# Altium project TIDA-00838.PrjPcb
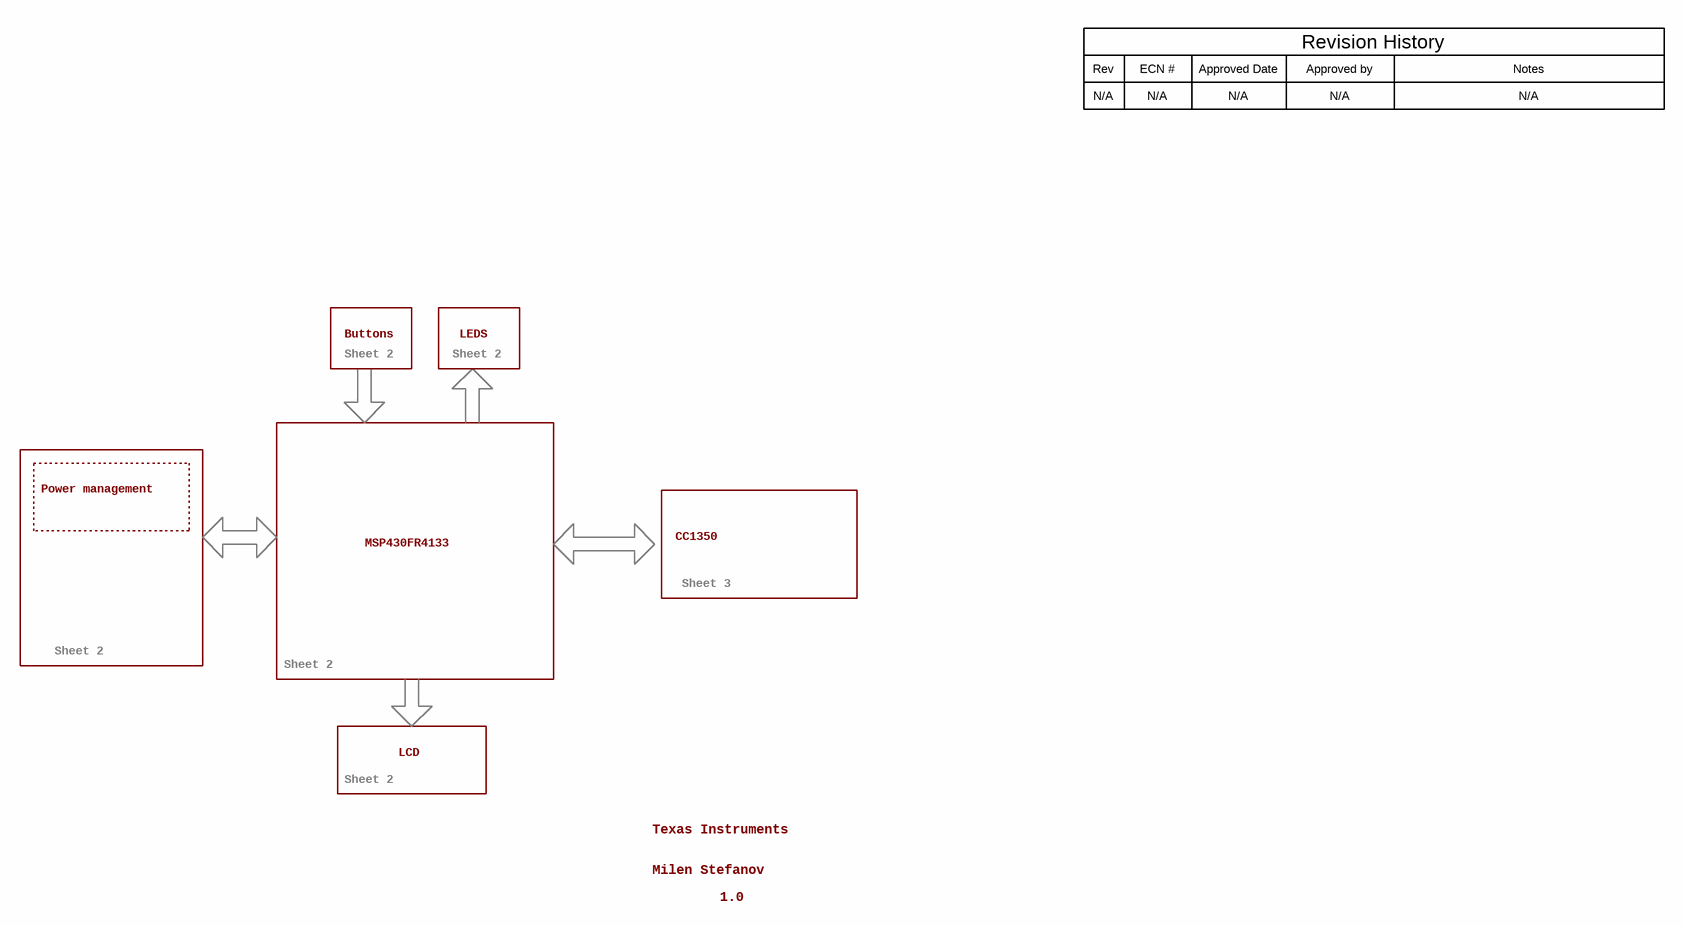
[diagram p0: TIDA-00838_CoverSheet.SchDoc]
TID: TIDA-00838; TechSupport: http://www.ti.com/support; SCH_Rev: E1; PRJ_Title: Heat Cost Allocator with wM-Bus @ 868MHz; PRJ_Number: TIDA-00838; PRJ_Engineer: Milen Stefanov; PRJ_Customer: Public Release; PCB_Rev: E1; PCB_Layout: a0797195; EVM_Orderable: N/A; CopyrightYear: 2015
4 sheets, 91 parts. Net scope: global (net labels, ports and power ports of the same name join across sheets).
Board file: TIDA-00838.PcbDoc
Sheets:
  TIDA-00838_CoverSheet.SchDoc
  TIDA-00838_TID_Hardware.SchDoc
  TIDA-00838_MCU.SchDoc
  TIDA-00838_RF.SchDoc

## Sheet TIDA-00838_CoverSheet.SchDoc
size 431 x 279 mm; Date: Not shown in title block; ApprovedBy: Not shown in title block; CheckedBy: Not shown in title block; Author: Not shown in title block; CompanyName: Not shown in title block; Engineer: Not shown in title block; Organization: Not shown in title block; Address1: Not shown in title block; Address2: Not shown in title block; Address3: Not shown in title block; Address4: Not shown in title block; DocumentNumber: 1; Revision: Use project parameter SCH_Rev; SheetNumber: 1; SheetTotal: 3; PageSetup: Record=PageOptions¦CenterHorizontal=True¦CenterVertical=True¦PrintScale=1.00¦XCorrection=1.00¦YCorrection=1.00¦PrintKind=0¦BorderSize=5000000¦LeftOffset=0¦BottomOffset=0¦Orientation=2¦PaperLength=1000¦PaperWidth=1000¦Scale=100¦PaperSource=15¦PrintQuality=600¦MediaType=1¦DitherType=10¦PaperKind=Letter¦PrintScaleMode=1

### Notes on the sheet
- Rev
- N/A
- ECN #
- Approved Date
- Approved by
- Revision History
- Notes
- Buttons
- Sheet 2
- LEDS
- Power management
- MSP430FR4133
- CC1350
- Sheet 3
- LCD
- Texas Instruments
- Milen Stefanov
- 1.0

## Sheet TIDA-00838_TID_Hardware.SchDoc
size 431 x 279 mm; Date: Not shown in title block; ApprovedBy: Not shown in title block; CheckedBy: Not shown in title block; Author: Not shown in title block; CompanyName: Not shown in title block; Engineer: Not shown in title block; Organization: Not shown in title block; Address1: Not shown in title block; Address2: Not shown in title block; Address3: Not shown in title block; Address4: Not shown in title block; DocumentNumber: 1; Revision: Use project parameter SCH_Rev; SheetNumber: 3; SheetTotal: 3; PageSetup: Record=PageOptions¦CenterHorizontal=True¦CenterVertical=True¦PrintScale=1.00¦XCorrection=1.00¦YCorrection=1.00¦PrintKind=0¦BorderSize=5000000¦LeftOffset=0¦BottomOffset=0¦Orientation=2¦PaperLength=1000¦PaperWidth=1000¦Scale=100¦PaperSource=15¦PrintQuality=600¦MediaType=1¦DitherType=10¦PaperKind=Letter¦PrintScaleMode=1
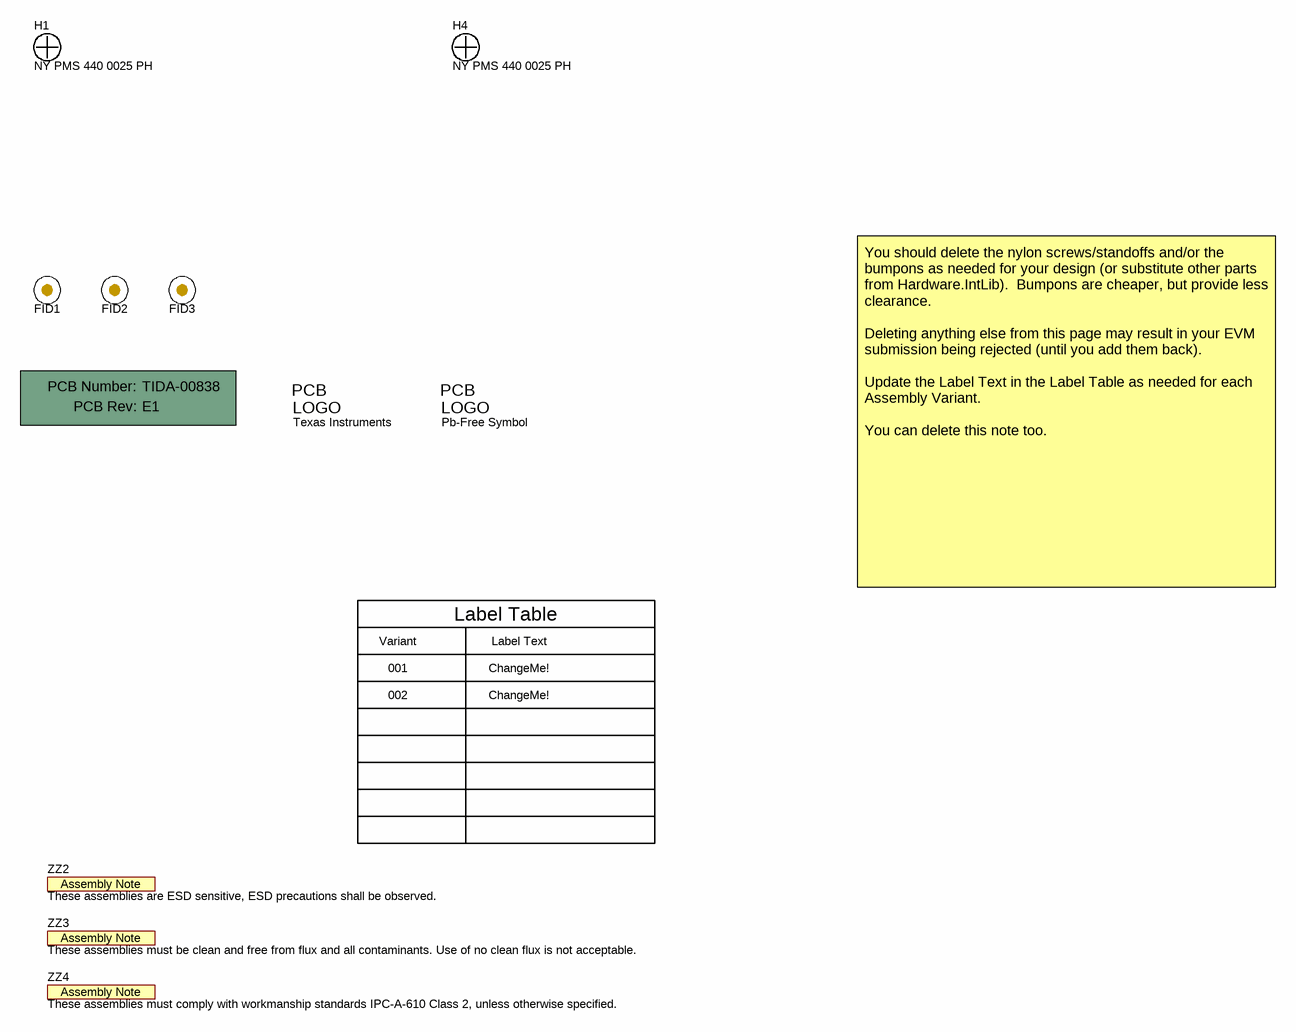
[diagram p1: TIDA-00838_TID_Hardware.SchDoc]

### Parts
!PCB  Printed Circuit Board  (value not drawn)  (mechanical)
FID1  Fiducial  [Fiducial10-20]  (value not drawn)
FID2  Fiducial  [Fiducial10-20]  (value not drawn)
FID3  Fiducial  [Fiducial10-20]  (value not drawn)
H1  NY PMS 440 0025 PH  [NY PMS 440 0025 PH]
H4  NY PMS 440 0025 PH  [NY PMS 440 0025 PH]
Logo1  Texas Instruments  [TI_Symbol_Overlay_Small]  (no BOM)
Logo2  Pb-Free Symbol  [Pb-Free_Overlay_Small]  (no BOM)
ZZ2  These assemblies are ESD sensitive, ESD precautions shall be observed.  [AssemblyNote]  (no BOM)
ZZ3  These assemblies must be clean and free from flux and all contaminants. Use of no clean flux is not acceptable.  [AssemblyNote]  (no BOM)
ZZ4  These assemblies must comply with workmanship standards IPC-A-610 Class 2, unless otherwise specified.  [AssemblyNote]  (no BOM)

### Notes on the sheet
- Variant
- Label Table
- Label Text
- You should delete the nylon screws/standoffs and/or the bumpons as needed for your design (or substitute other parts from Hardware.IntLib).  Bumpons are cheaper, but provide less clearance.
  Deleting anything else from this page may result in your EVM submission being rejected (until you add them back).
  Update the Label Text in the Label Table as needed for each Assembly Variant.
  You can delete this note too.
- 001
- 002
- ChangeMe!

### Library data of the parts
!PCB = PCB: Manufacturer: Any; PartNumber: TIDA-00838; SymbolCreator: a0412235
FID1-FID3 = Fiducial: Fiducial mark.  There is nothing to buy or mount.; SymbolCreator: codlsc
H1 H4 = NY PMS 440 0025 PH: Machine Screw, Round, #4-40 x 1/4, Nylon, Philips panhead; Manufacturer: B&F Fastener Supply; CompType: Hardware; SymbolCreator: codlsc; U/M: EA
Logo1 = TI_Logo: Texas Instrument Corporate Signature; SymbolCreator: codlsc
Logo2 = Pb-Free: SymbolCreator: a0412235
ZZ2-ZZ4 = AssemblyNote: SymbolCreator: codlsc

## Sheet TIDA-00838_MCU.SchDoc
size 431 x 279 mm; Date: Not shown in title block; ApprovedBy: Not shown in title block; CheckedBy: Not shown in title block; Author: Not shown in title block; CompanyName: Not shown in title block; Engineer: Not shown in title block; Organization: Not shown in title block; Address1: Not shown in title block; Address2: Not shown in title block; Address3: Not shown in title block; Address4: Not shown in title block; DocumentNumber: 1; Revision: Use project parameter SCH_Rev; SheetNumber: 2; SheetTotal: 3; PageSetup: Record=PageOptions¦CenterHorizontal=True¦CenterVertical=True¦PrintScale=0.62¦XCorrection=1.00¦YCorrection=1.00¦PrintKind=0¦BorderSize=5000000¦LeftOffset=0¦BottomOffset=0¦Orientation=2¦PaperLength=2794¦PaperWidth=2159¦Scale=100¦PaperSource=7¦PrintQuality=600¦MediaType=1¦DitherType=10¦PrintScaleMode=1¦PaperKind=8 1/2x11¦PaperIndex=1
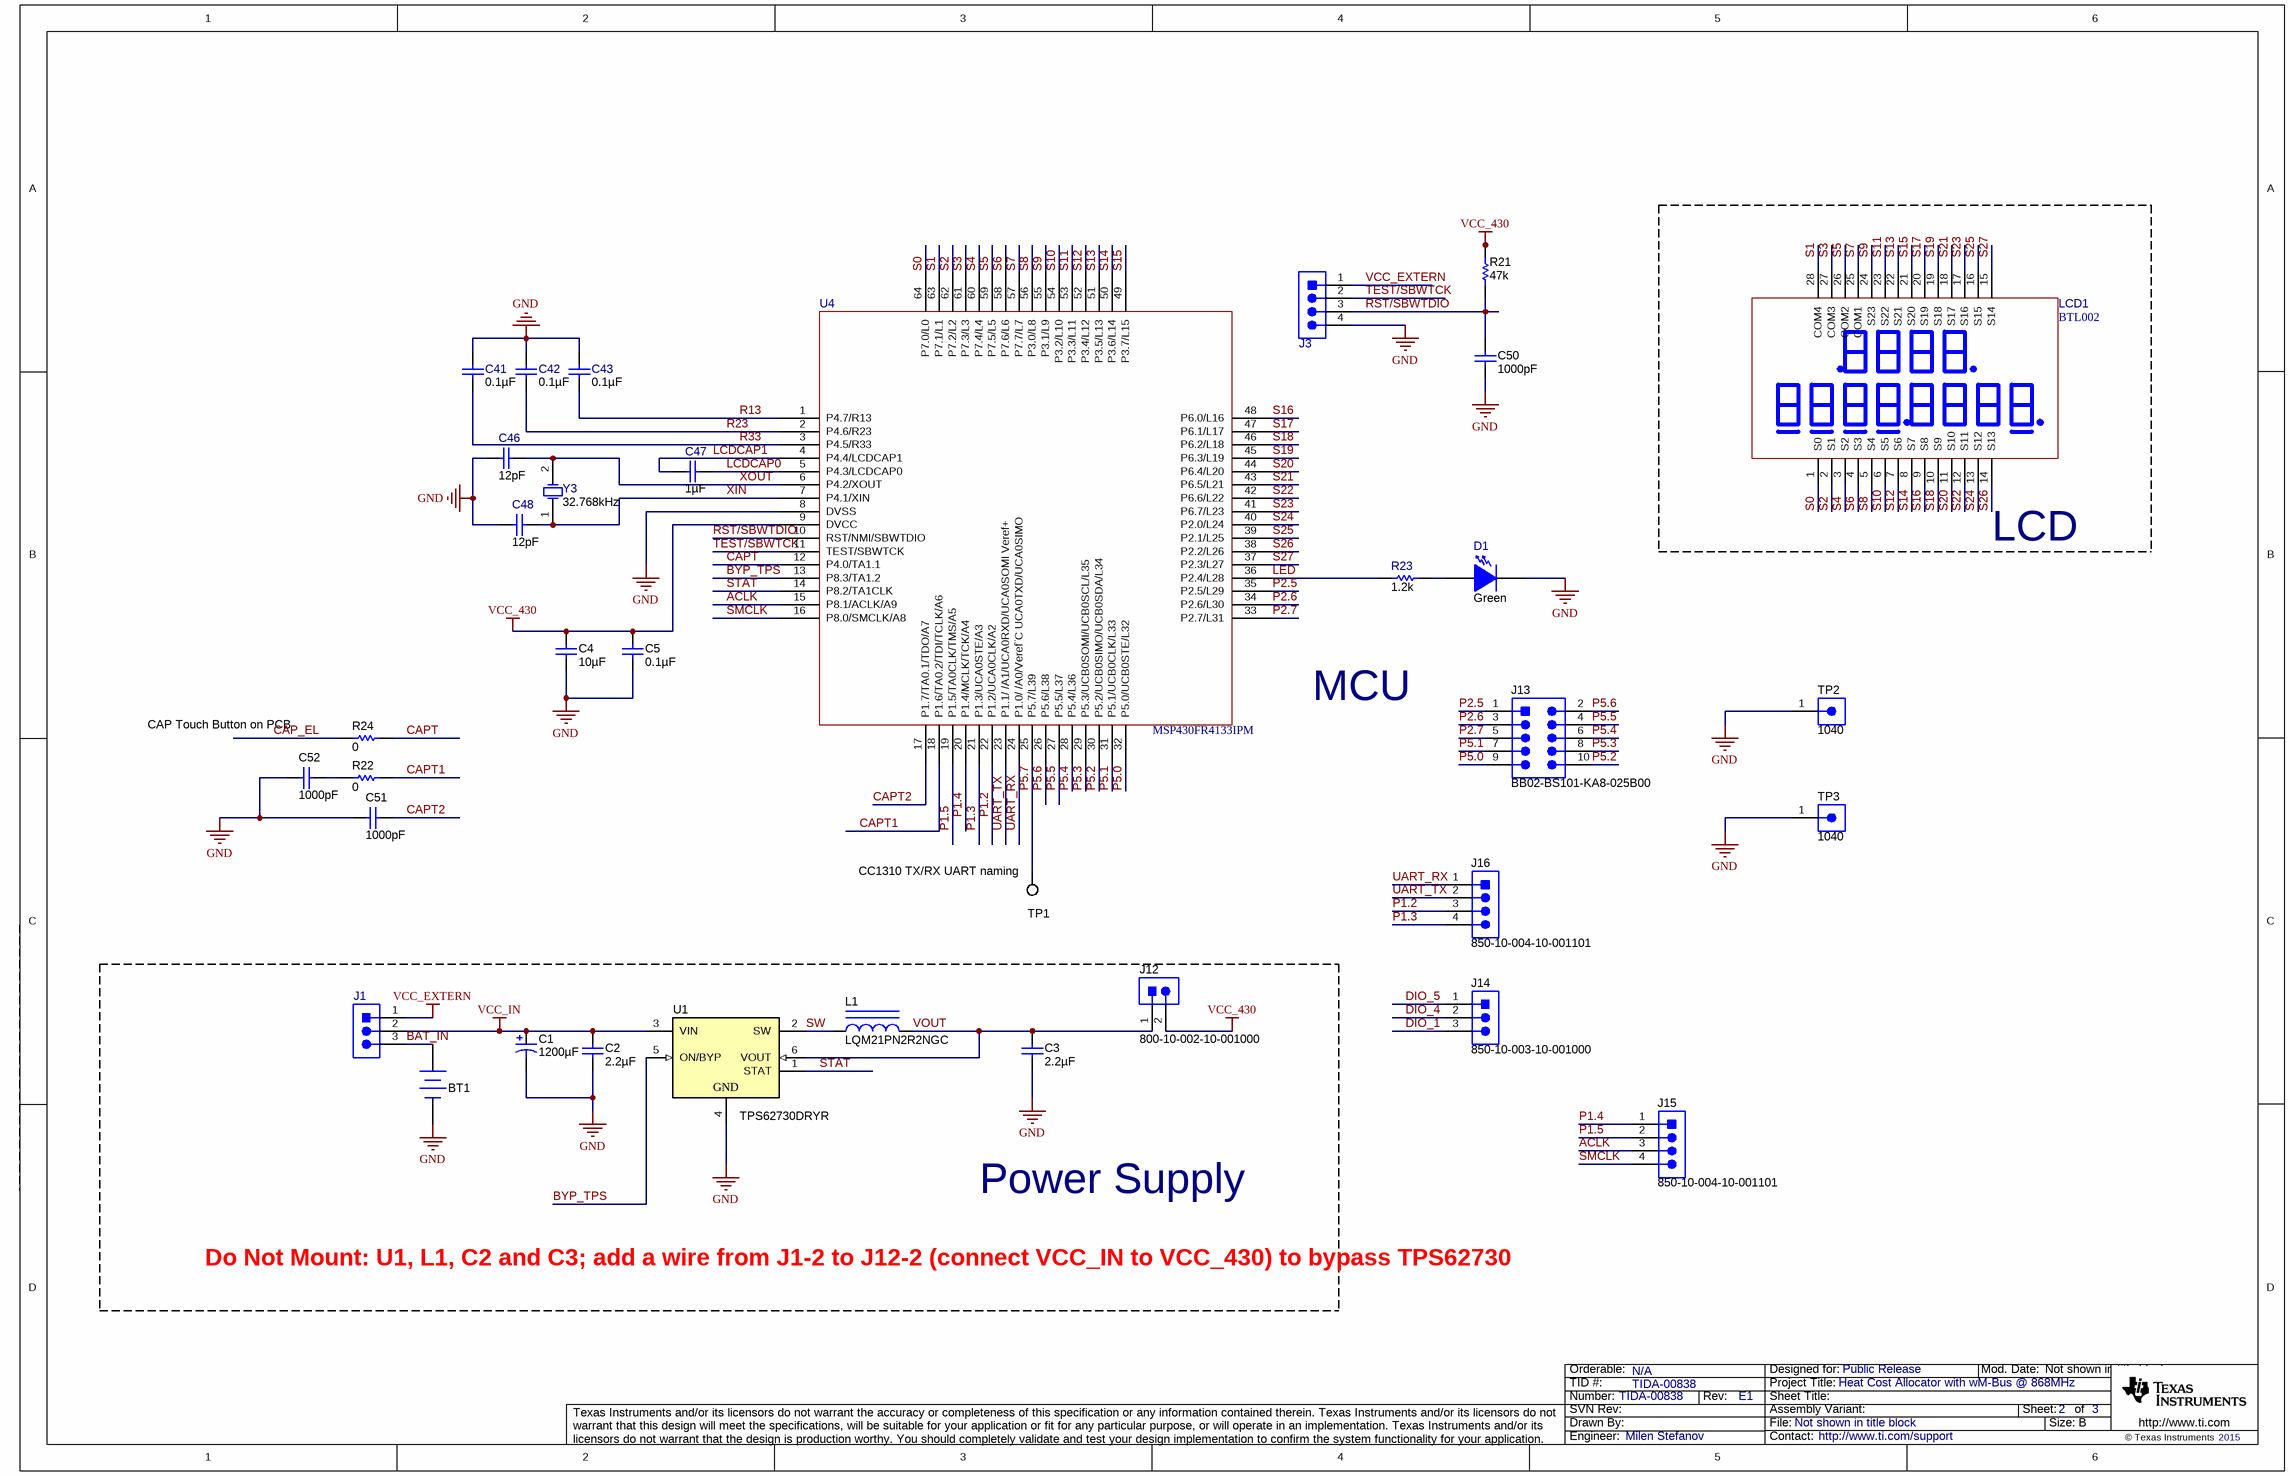
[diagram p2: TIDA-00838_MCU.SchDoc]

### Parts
BT1  1010  [BAT_1010]  (value not drawn)
C1  ValueDisplayed: 1200µF  [CAPPR5-10X20]  (hidden comment: EEUFM1A122)
C2  ValueDisplayed: 2.2µF  [0402]  (hidden comment: GRM155R60J225ME15D)
C3  ValueDisplayed: 2.2µF  [0402]  (hidden comment: GRM155R60J225ME15D)
C4  ValueDisplayed: 10µF  [0603S]  (hidden comment: GRM188R61A106ME69)
C5  ValueDisplayed: 0.1µF  [0402S]  (hidden comment: GRM155R61E104KA87D)
C41  ValueDisplayed: 0.1µF  [0402S]  (hidden comment: GRM155R61E104KA87D)
C42  ValueDisplayed: 0.1µF  [0402S]  (hidden comment: GRM155R61E104KA87D)
C43  ValueDisplayed: 0.1µF  [0402S]  (hidden comment: GRM155R61E104KA87D)
C46  ValueDisplayed: 12pF  [0402S]  (hidden comment: GRM1555C1H120JA01D)
C47  ValueDisplayed: 1µF  [0402S]  (hidden comment: GRM155R61A105KE15D)
C48  ValueDisplayed: 12pF  [0402S]  (hidden comment: GRM1555C1H120JA01D)
C50  ValueDisplayed: 1000pF  [0402S]  (hidden comment: GRM155R61H102KA01D)
C51  ValueDisplayed: 1000pF  [0402S]  (hidden comment: GRM155R61H102KA01D)
C52  ValueDisplayed: 1000pF  [0402S]  (hidden comment: GRM155R61H102KA01D)
D1  value Green  [LED_LTST-C170]  (hidden comment: LTST-C170KRKT)
J1  TSW-103-07-G-S  [TSW-103-07-G-S]  (value not drawn)
J3  TSW-104-07-G-S  [TSW-104-07-G-S]  (value not drawn)
J12  800-10-002-10-001000  [Mill-Max_800-10-002-10-001000]
J13  BB02-BS101-KA8-025B00  [Gradconn_BB02-BS101-xAx-025B00]
J14  850-10-003-10-001000  [Mill-Max_850-10-003-10-001000]
J15  850-10-004-10-001101  [Preci-dip_850-xx-004-10-001101]
J16  850-10-004-10-001101  [Preci-dip_850-xx-004-10-001101]
L1  LQM21PN2R2NGC  [0805_HV]
LCD1  BTL002  [LCD]
R21  ValueDisplayed: 47k  [0603S]  (hidden comment: CRCW060347K0JNEA)
R22  ValueDisplayed: 0  [0402S]  (hidden comment: CRCW04020000Z0ED)
R23  ValueDisplayed: 1.2k  [0603]  (hidden comment: CRCW06031K20JNEA)
R24  ValueDisplayed: 0  [0402S]  (hidden comment: CRCW04020000Z0ED)
TP1  5015  [Testpoint_Keystone_Miniature]  (value not drawn)
TP2  1040  [CONN_1040]
TP3  1040  [CONN_1040]
U1  TPS62730DRYR  [DRY0006A]
U4  MSP430FR4133IPM  [PM0064A_M]
Y3  Frequency: 32.768kHz  [XTAL_MS3V-T1R]  (hidden comment: MS3V-T1R 32.768KHZ +/-20PPM 12.5PF)

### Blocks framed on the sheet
LCD: LCD1
Power Supply: BT1 C1-C3 J1 J12 L1 U1

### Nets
GND: BT1.2(-) C1.2(-) C2.2 C3.2 C4.2 C5.2 C41.1 C42.1 C43.1 C46.1 C48.1 C50.2 C51.1 C52.1 D1.2(K) J3.4 TP2.1 TP3.1 U1.4(GND) U4.8(DVSS)
VCC_430: C4.1 C5.1 J12.2 R21.2 U4.9(DVCC)
VCC_EXTERN: J1.1 J3.1
VCC_IN: C1.1(+) C2.1 J1.2 U1.3(VIN)
ACLK: J15.3 U4.15(P8.1/ACLK/A9)
BAT_IN: BT1.1(+) J1.3
BYP_TPS: U1.5(ON/BYP) U4.13(P8.3/TA1.2)
CAP_EL: R24.1
CAPT: R24.2 U4.12(P4.0/TA1.1)
CAPT1: R22.2 U4.18(P1.6/TA0.2/TDI/TCLK/A6)
CAPT2: C51.2 U4.17(P1.7/TA0.1/TDO/A7)
DIO_1: J14.3
DIO_4: J14.2
DIO_5: J14.1
LCDCAP0: C47.2 U4.5(P4.3/LCDCAP0)
LCDCAP1: C47.1 U4.4(P4.4/LCDCAP1)
LED: R23.1 U4.36(P2.4/L28)
P1.2: J16.3 U4.22(P1.2/UCA0CLK/A2)
P1.3: J16.4 U4.21(P1.3/UCA0STE/A3)
P1.4: J15.1 U4.20(P1.4/MCLK/TCK/A4)
P1.5: J15.2 U4.19(P1.5/TA0CLK/TMS/A5)
P2.5: J13.1 U4.35(P2.5/L29)
P2.6: J13.3 U4.34(P2.6/L30)
P2.7: J13.5 U4.33(P2.7/L31)
P5.0: J13.9 U4.32(P5.0/UCB0STE/L32)
P5.1: J13.7 U4.31(P5.1/UCB0CLK/L33)
P5.2: J13.10 U4.30(P5.2/UCB0SIMO/UCB0SDA/L34)
P5.3: J13.8 U4.29(P5.3/UCB0SOMI/UCB0SCL/L35)
P5.4: J13.6 U4.28(P5.4/L36)
P5.5: J13.4 U4.27(P5.5/L37)
P5.6: J13.2 U4.26(P5.6/L38)
P5.7: TP1.1 U4.25(P5.7/L39)
R13: C43.2 U4.1(P4.7/R13)
R23: C42.2 U4.2(P4.6/R23)
R33: C41.2 U4.3(P4.5/R33)
RST/SBWTDIO: C50.1 J3.3 R21.1 U4.10(RST/NMI/SBWTDIO)
S0: LCD1.1(S0) U4.64(P7.0/L0)
S1: LCD1.28(COM4) U4.63(P7.1/L1)
S2: LCD1.2(S1) U4.62(P7.2/L2)
S3: LCD1.27(COM3) U4.61(P7.3/L3)
S4: LCD1.3(S2) U4.60(P7.4/L4)
S5: LCD1.26(COM2) U4.59(P7.5/L5)
S6: LCD1.4(S3) U4.58(P7.6/L6)
S7: LCD1.25(COM1) U4.57(P7.7/L7)
S8: LCD1.5(S4) U4.56(P3.0/L8)
S9: LCD1.24(S23) U4.55(P3.1/L9)
S10: LCD1.6(S5) U4.54(P3.2/L10)
S11: LCD1.23(S22) U4.53(P3.3/L11)
S12: LCD1.7(S6) U4.52(P3.4/L12)
S13: LCD1.22(S21) U4.51(P3.5/L13)
S14: LCD1.8(S7) U4.50(P3.6/L14)
S15: LCD1.21(S20) U4.49(P3.7/L15)
S16: LCD1.9(S8) U4.48(P6.0/L16)
S17: LCD1.20(S19) U4.47(P6.1/L17)
S18: LCD1.10(S9) U4.46(P6.2/L18)
S19: LCD1.19(S18) U4.45(P6.3/L19)
S20: LCD1.11(S10) U4.44(P6.4/L20)
S21: LCD1.18(S17) U4.43(P6.5/L21)
S22: LCD1.12(S11) U4.42(P6.6/L22)
S23: LCD1.17(S16) U4.41(P6.7/L23)
S24: LCD1.13(S12) U4.40(P2.0/L24)
S25: LCD1.16(S15) U4.39(P2.1/L25)
S26: LCD1.14(S13) U4.38(P2.2/L26)
S27: LCD1.15(S14) U4.37(P2.3/L27)
SMCLK: J15.4 U4.16(P8.0/SMCLK/A8)
STAT: U1.1(STAT) U4.14(P8.2/TA1CLK)
SW: L1.1 U1.2(SW)
TEST/SBWTCK: J3.2 U4.11(TEST/SBWTCK)
UART_RX: J16.1 U4.24(P1.0/_/A0/Veref¨C_UCA0TXD/UCA0SIMO)
UART_TX: J16.2 U4.23(P1.1/_/A1/UCA0RXD/UCA0SOMI_Veref+)
VOUT: C3.1 J12.1 L1.2 U1.6(VOUT)
XIN: C48.2 U4.7(P4.1/XIN) Y3.1(OSC1)
XOUT: C46.2 U4.6(P4.2/XOUT) Y3.2(OSC2)
NetC52_2: C52.2 R22.1
NetD1_1: D1.1(A) R23.2

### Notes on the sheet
- CAP Touch Button on PCB
- MCU
- (near TP1) CC1310 TX/RX UART naming
- Do Not Mount: U1, L1, C2 and C3; add a wire from J1-2 to J12-2 (connect VCC_IN to VCC_430) to bypass TPS62730

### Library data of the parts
BT1 = 1010: Battery Holder, Nylon, CR2, SMT; Manufacturer: Keystone
C1 = EEUFM1A122: CAP, AL, 1200 µF, 10 V, +/- 20%, TH; Manufacturer: Panasonic; Polarized: Y; CompType: Capacitor; Value: 1200uF; U/M: EA; Cap_F: 0.0012; Tolerance_%: 20; Value1: Unknown; VDC_V: 10; Value2: 10V; TaMin_C: -40; TaMax_C: 105; Cap_Case: 10x20
C2 C3 = GRM155R60J225ME15D: CAP, CERM, 2.2 µF, 6.3 V, +/- 20%, X5R, 0402; Manufacturer: MuRata; Polarized: N; CompType: Capacitor; Value: 2.2uF; U/M: EA; Cap_F: 0.0000022; Tolerance_%: 20; ESR_ohm: 0.005; Value1: 0.005 ohm; VDC_V: 6.3; Value2: 6.3V; IRMS_A: 3.67; TaMin_C: -55; TaMax_C: 125
C4 = GRM188R61A106ME69: CAP, CERM, 10 µF, 10 V, +/- 20%, X5R, 0603; Manufacturer: MuRata; Polarized: N; CompType: Capacitor; Value: 10uF; U/M: EA; Cap_F: 0.00001; Tolerance_%: 20; Value1: Unknown; VDC_V: 10; Value2: 10V; TaMin_C: -55; TaMax_C: 85; Cap_Case: 0603
C5 C41-C43 = GRM155R61E104KA87D: CAP, CERM, 0.1 µF, 25 V, +/- 10%, X5R, 0402; Manufacturer: MuRata; Polarized: N; CompType: Capacitor; Value: 0.1uF; U/M: EA; Cap_F: 0.0000001; Tolerance_%: 10; Value1: Unknown; VDC_V: 25; Value2: 25V; TaMin_C: -55; TaMax_C: 85; Cap_Case: 0402
C46 C48 = GRM1555C1H120JA01D: CAP, CERM, 12 pF, 50 V, +/- 5%, C0G/NP0, 0402; Manufacturer: MuRata; Polarized: N; CompType: Capacitor; Value: 12pF; U/M: EA; Cap_F: 0.000000000012; Tolerance_%: 5; Value1: Unknown; VDC_V: 50; Value2: 50V; TaMin_C: -55; TaMax_C: 125; Cap_Case: 0402
C47 = GRM155R61A105KE15D: CAP, CERM, 1 µF, 10 V, +/- 10%, X5R, 0402; Manufacturer: MuRata; Polarized: N; CompType: Capacitor; Value: 1uF; U/M: EA; Cap_F: 0.000001; Tolerance_%: 10; Value1: Unknown; Value2: 10V; TaMin_C: -55; TaMax_C: 85; Cap_Case: 0402
C50-C52 = GRM155R61H102KA01D: CAP, CERM, 1000 pF, 50 V, +/- 10%, X5R, 0402; Manufacturer: MuRata; Polarized: N; CompType: Capacitor; Value: 1000pF; U/M: EA; Cap_F: 0.000000001; Tolerance_%: 10; Value1: Unknown; VDC_V: 50; Value2: 50V; TaMin_C: -55; TaMax_C: 85; Cap_Case: 0402
D1 = LTST-C170KRKT: LED, Green, SMD; Manufacturer: Lite-On; Type: AlInGaP; Vf_V: 2; Value2: 2V; Io_A: 20; Value1: W; Color: red; U/M: EA
J1 = TSW-103-07-G-S: Header, TH, 100mil, 3x1, Gold plated, 230 mil above insulator; Manufacturer: Samtec; SymbolCreator: a0799628; U/M: EA
J3 = TSW-104-07-G-S: Header, TH, 100mil, 4x1, Gold plated, 230 mil above insulator; Manufacturer: Samtec; SymbolCreator: a0412235; U/M: EA
J12 = 800-10-002-10-001000: Header, 100mil, 2x1, TH; Manufacturer: Mill-Max; SymbolCreator: a0412235; U/M: EA
J13 = BB02-BS101-KA8-025B00: Header, 1.27mm, 5x2, SMT; Manufacturer: GradConn; SymbolCreator: a0412235; U/M: EA
J14 = 850-10-003-10-001000: Header, 50mil, 3x1, Gold, TH; Manufacturer: Mill-Max; SymbolCreator: a0799628; U/M: EA
J15 J16 = 850-10-004-10-001101: Header, 50mil, 4x1, Gold, TH; Manufacturer: Preci-Dip; SymbolCreator: a0412235; U/M: EA
L1 = LQM21PN2R2NGC: Inductor, Shielded, Ferrite, 2.2 µH, 0.8 A, 0.23 ohm, SMD; Manufacturer: MuRata; Value: 2.2uH; Ind_H: 2.2E-6; ValueDisplayed: 2.2µH; Imax_A: 0.8; Irms: 0.8A @ 0C rise; DCR_ohm: 0.23; Value2: 0.8A
LCD1 = LCD_4MUX: BTL002 4COM LCD
R21 = CRCW060347K0JNEA: RES, 47 k, 5%, 0.1 W, 0603; Manufacturer: Vishay-Dale; CompType: Resistor; Value: 47k; Res_ohm: 47000; Value_Code: 47k0; Tolerance_%: 5; Power_W: 0.1; Value2: 0.1W; VDC_V: 75; TempCo: 200 ppm/C; EIA_Code: E24; U/M: EA
R22 R24 = CRCW04020000Z0ED: RES, 0, 5%, 0.063 W, 0402; Manufacturer: Vishay-Dale; CompType: Resistor; Value: 0; Value_Code: 0000; Tolerance_%: 5; Power_W: 0.063; Value2: 0.063W; VDC_V: 50; TempCo: 200 ppm/C; EIA_Code: E24; U/M: EA
R23 = CRCW06031K20JNEA: RES, 1.2 k, 5%, 0.1 W, 0603; Manufacturer: Vishay-Dale; CompType: Resistor; Value: 1.2k; Res_ohm: 1200; Value_Code: 1k20; Tolerance_%: 5; Power_W: 0.1; Value2: 0.1W; VDC_V: 75; TempCo: 200 ppm/C; EIA_Code: E24; U/M: EA
TP1 = 5015: Test Point, Miniature, SMT; Manufacturer: Keystone; CompType: Test Point Loop; U/M: EA
TP2 TP3 = 1040: TEST POINT SLOTTED .118", TH; Manufacturer: Keystone; CompType: Test Point Loop; U/M: EA; SymbolCreator: a0412235
U1 = TPS62730DRYR: Buck Step Down Regulator with 1.9 to 3.9 V Input and 2.1 V Output, -40 to 85 degC, 6-Pin SON (DRY), Green (RoHS & no Sb/Br); Manufacturer: Texas Instruments; Alternate PartNumber: Equivalent; Duty Cycle(Max)(%): 100; Iout(Max)(A): 0.1; Rating: Catalog; Regulated Outputs(#): 1; SubFamily: Step-Down Regulator; Synchronous Rectification: TRUE; Vin(Max)(V): 3.9; Vin(Min)(V): 1.9; Vout(Max)(V): 2.1
U4 = MSP430G60x1: 16-bit Ultra-Low-Power MCU; Manufacturer: Texas Instruments
Y3 = MS3V-T1R 32.768KHZ +/-20PPM 12.5PF: Crystal, 32.768kHz, 12.5pF, SMD; Manufacturer: Micro Crystal AG; SymbolCreator: a0412235; U/M: EA; TaMin_C: -40; TaMax_C: 85; Frequency Stability: ?0ppm

## Sheet TIDA-00838_RF.SchDoc
size 431 x 279 mm; Date: Not shown in title block; ApprovedBy: Not shown in title block; CheckedBy: Not shown in title block; Author: Not shown in title block; CompanyName: Not shown in title block; Engineer: Not shown in title block; Organization: Not shown in title block; Address1: Not shown in title block; Address2: Not shown in title block; Address3: Not shown in title block; Address4: Not shown in title block; DocumentNumber: 1; Revision: Use project parameter SCH_Rev; SheetNumber: 2; SheetTotal: 3; PageSetup: Record=PageOptions¦CenterHorizontal=True¦CenterVertical=True¦PrintScale=0.62¦XCorrection=1.00¦YCorrection=1.00¦PrintKind=0¦BorderSize=5000000¦LeftOffset=0¦BottomOffset=0¦Orientation=2¦PaperLength=2794¦PaperWidth=2159¦Scale=100¦PaperSource=7¦PrintQuality=600¦MediaType=1¦DitherType=10¦PrintScaleMode=1¦PaperKind=8 1/2x11¦PaperIndex=1
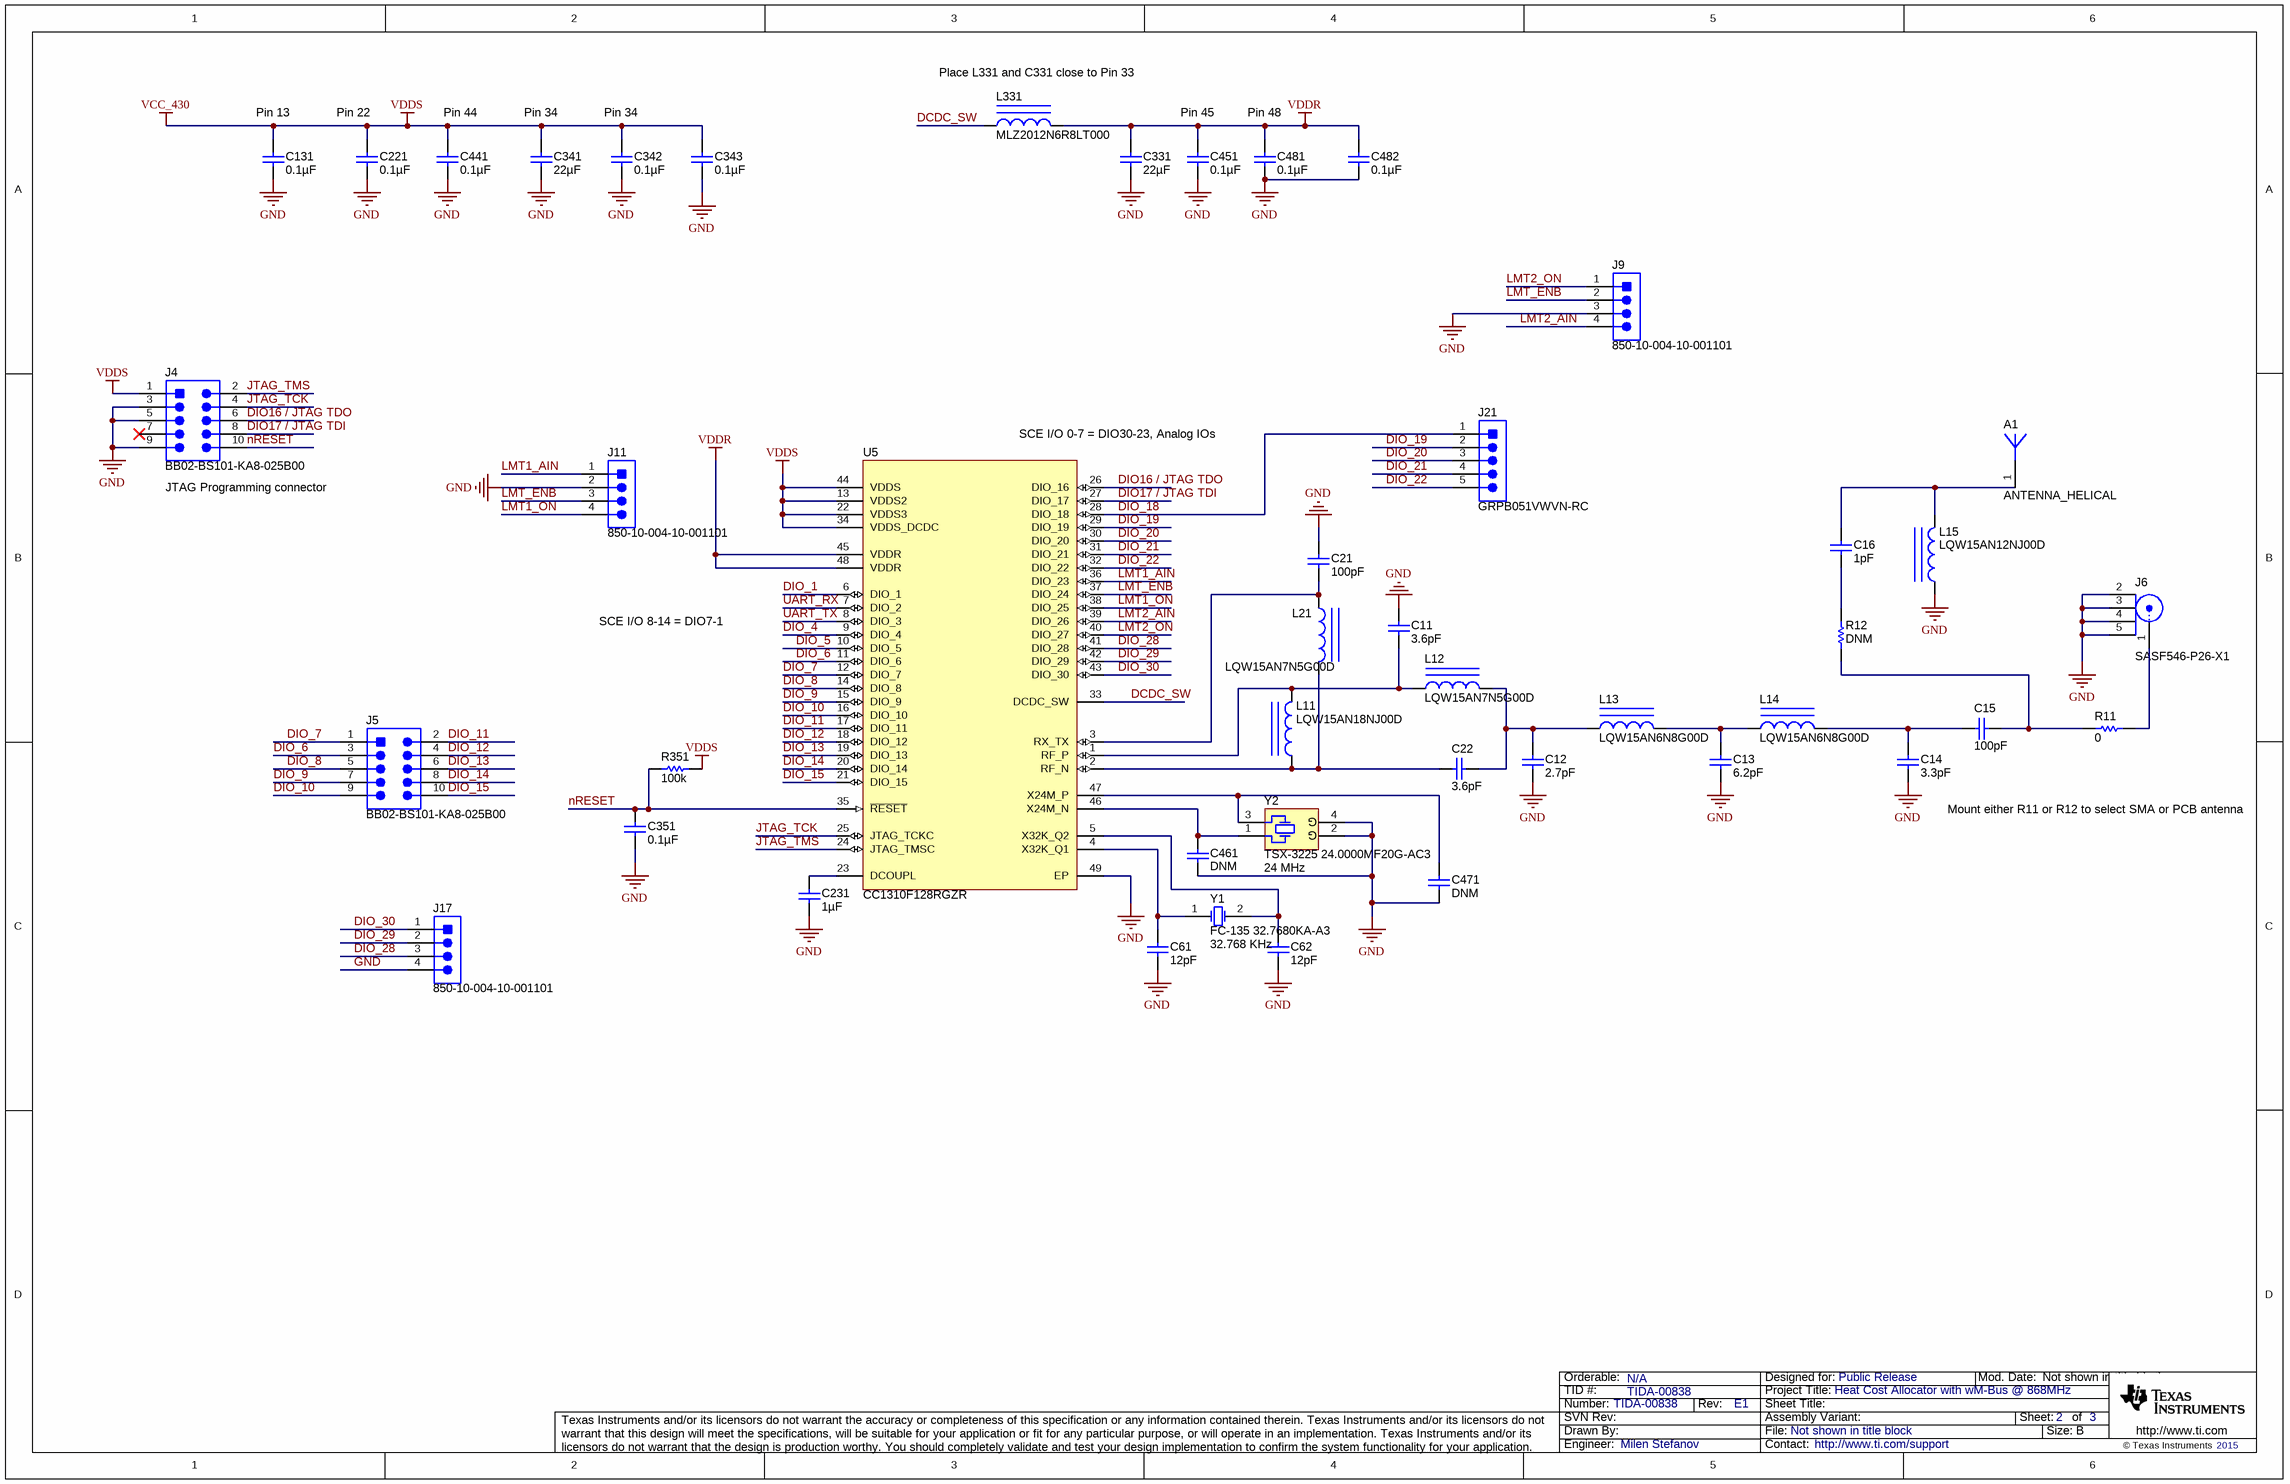
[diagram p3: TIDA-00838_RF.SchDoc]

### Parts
A1  ANTENNA_HELICAL  [ANTENNA_HELICAL]  (net tie)
C11  ValueDisplayed: 3.6pF  [0402S]  (hidden comment: Comment)
C12  ValueDisplayed: 2.7pF  [0402S]  (hidden comment: GRM1555C1H2R7CA01D)
C13  ValueDisplayed: 6.2pF  [0402S]  (hidden comment: GRM1555C1H6R2CA01D)
C14  ValueDisplayed: 3.3pF  [0402S]  (hidden comment: GRM1555C1H3R3CA01D)
C15  ValueDisplayed: 100pF  [0402S]  (hidden comment: GRM1555C1H101JA01D)
C16  ValueDisplayed: 1pF  [0402S]  (hidden comment: GRM1555C1H1R0CA01D)
C21  ValueDisplayed: 100pF  [0402S]  (hidden comment: GRM1555C1H101JA01D)
C22  ValueDisplayed: 3.6pF  [0402S]  (hidden comment: GRM1555C1H3R6CA01D)
C61  ValueDisplayed: 12pF  [0402S]  (hidden comment: Comment)
C62  ValueDisplayed: 12pF  [0402S]  (hidden comment: GRM1555C1H120JA01D)
C131  ValueDisplayed: 0.1µF  [0402S]  (hidden comment: GRM155R61E104KA87D)
C221  ValueDisplayed: 0.1µF  [0402S]  (hidden comment: GRM155R61E104KA87D)
C231  ValueDisplayed: 1µF  [0402S]  (hidden comment: Comment)
C331  ValueDisplayed: 22µF  [0603S]  (hidden comment: GRM188R60J226MEA0J)
C341  ValueDisplayed: 22µF  [0603S]  (hidden comment: GRM188R60J226MEA0J)
C342  ValueDisplayed: 0.1µF  [0402S]  (hidden comment: GRM155R61E104KA87D)
C343  ValueDisplayed: 0.1µF  [0402S]  (hidden comment: GRM155R61E104KA87D)
C351  ValueDisplayed: 0.1µF  [0402S]  (hidden comment: GRM155R61E104KA87D)
C441  ValueDisplayed: 0.1µF  [0402S]  (hidden comment: GRM155R61E104KA87D)
C451  ValueDisplayed: 0.1µF  [0402S]  (hidden comment: GRM155R61E104KA87D)
C461  DNM  [0402S]
C471  DNM  [0402S]
C481  ValueDisplayed: 0.1µF  [0402S]  (hidden comment: GRM155R61E104KA87D)
C482  ValueDisplayed: 0.1µF  [0402S]  (hidden comment: GRM155R61E104KA87D)
J4  BB02-BS101-KA8-025B00  [Gradconn_BB02-BS101-xAx-025B00]
J5  BB02-BS101-KA8-025B00  [Gradconn_BB02-BS101-xAx-025B00]
J6  SASF546-P26-X1  [CONN_LTI_SASF546-P26-X1]
J9  850-10-004-10-001101  [Preci-dip_850-xx-004-10-001101]
J11  850-10-004-10-001101  [Preci-dip_850-xx-004-10-001101]
J17  850-10-004-10-001101  [Preci-dip_850-xx-004-10-001101]
J21  GRPB051VWVN-RC  [Sullins_GRPB051VWVN-RC]
L11  LQW15AN18NJ00D  [LQW15A_00_10]
L12  LQW15AN7N5G00D  [LQW15A_00_10]
L13  LQW15AN6N8G00D  [LQW15A_00_10]
L14  LQW15AN6N8G00D  [LQW15A_00_10]
L15  LQW15AN12NJ00D  [LQW15A_00_10]
L21  LQW15AN7N5G00D  [LQW15A_00_10]
L331  MLZ2012N6R8LT000  [0805_145]
R11  ValueDisplayed: 0  [0402S]  (hidden comment: CRCW04020000Z0ED)
R12  ValueDisplayed: DNM  [0402S]  (hidden comment: Comment)
R351  ValueDisplayed: 100k  [0402S]  (hidden comment: ERJ-2RKF1003X)
U5  CC1310F128RGZR  [RGZ0048A]
Y1  FC-135 32.7680KA-A3  Frequency: 32.768 KHz  [Epson_FC-135]
Y2  TSX-3225 24.0000MF20G-AC3  Frequency: 24 MHz  [EPSON_TSX-3225]

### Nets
GND: C11.1 C12.2 C13.2 C14.2 C21.1 C61.2 C62.2 C131.2 C221.2 C231.2 C331.2 C341.2 C342.2 C343.2 C351.2 C441.2 C451.2 C461.2 C471.2 C481.2 C482.2 J4.3 J4.5 J4.9 J6.2 J6.3 J6.4 J6.5 J9.3 J11.2 J17.4 L15.1 U5.49(EP) Y2.2(GND) Y2.4(GND)
VCC_430: C131.1 C221.1 C341.1 C342.1 C343.1 C441.1 J4.1 R351.2 U5.13(VDDS2) U5.22(VDDS3) U5.34(VDDS_DCDC) U5.44(VDDS)  [also labelled VDDS]
VDDR: C331.1 C451.1 C481.1 C482.1 L331.2 U5.45(VDDR) U5.48(VDDR)
DCDC_SW: L331.1 U5.33(DCDC_SW)
DIO16 / JTAG TDO: J4.6 U5.26(DIO_16)
DIO17 / JTAG TDI: J4.8 U5.27(DIO_17)
DIO_1: U5.6(DIO_1)
DIO_4: U5.9(DIO_4)
DIO_5: U5.10(DIO_5)
DIO_6: J5.3 U5.11(DIO_6)
DIO_7: J5.1 U5.12(DIO_7)
DIO_8: J5.5 U5.14(DIO_8)
DIO_9: J5.7 U5.15(DIO_9)
DIO_10: J5.9 U5.16(DIO_10)
DIO_11: J5.2 U5.17(DIO_11)
DIO_12: J5.4 U5.18(DIO_12)
DIO_13: J5.6 U5.19(DIO_13)
DIO_14: J5.8 U5.20(DIO_14)
DIO_15: J5.10 U5.21(DIO_15)
DIO_18: J21.1 U5.28(DIO_18)
DIO_19: J21.2 U5.29(DIO_19)
DIO_20: J21.3 U5.30(DIO_20)
DIO_21: J21.4 U5.31(DIO_21)
DIO_22: J21.5 U5.32(DIO_22)
DIO_28: J17.3 U5.41(DIO_28)
DIO_29: J17.2 U5.42(DIO_29)
DIO_30: J17.1 U5.43(DIO_30)
JTAG_TCK: J4.4 U5.25(JTAG_TCKC)
JTAG_TMS: J4.2 U5.24(JTAG_TMSC)
LMT1_AIN: J11.1 U5.36(DIO_23)
LMT1_ON: J11.4 U5.38(DIO_25)
LMT2_AIN: J9.4 U5.39(DIO_26)
LMT2_ON: J9.1 U5.40(DIO_27)
LMT_ENB: J9.2 J11.3 U5.37(DIO_24)
nRESET: C351.1 J4.10 R351.1 U5.35(~{RESET})
UART_RX: U5.7(DIO_2)
UART_TX: U5.8(DIO_3)
NetA1_1: A1.1 C16.1 L15.2
NetC11_2: C11.2 L11.2 L12.1 U5.1(RF_P)
NetC12_1: C12.1 C22.2 L12.2 L13.1
NetC13_1: C13.1 L13.2 L14.1
NetC14_1: C14.1 C15.1 L14.2
NetC15_2: C15.2 R11.1 R12.1
NetC16_2: C16.2 R12.2
NetC21_2: C21.2 L21.1 U5.3(RX_TX)
NetC22_1: C22.1 L11.1 L21.2 U5.2(RF_N)
NetC61_1: C61.1 U5.4(X32K_Q1) Y1.1(OSC1)
NetC62_1: C62.1 U5.5(X32K_Q2) Y1.2(OSC2)
NetC231_1: C231.1 U5.23(DCOUPL)
NetC461_1: C461.1 U5.46(X24M_N) Y2.1
NetC471_1: C471.1 U5.47(X24M_P) Y2.3
NetJ6_1: J6.1 R11.2

Not connected (* = marked no-connect by the designer): J4 7*

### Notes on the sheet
- Place L331 and C331 close to Pin 33
- (near C131) Pin 13
- (near C221) Pin 22
- (near C441) Pin 44
- (near C341) Pin 34
- (near C342) Pin 34
- (near C451) Pin 45
- (near C481) Pin 48
- (near U5) SCE I/O 0-7 = DIO30-23, Analog IOs
- (near J4) JTAG Programming connector
- SCE I/O 8-14 = DIO7-1
- (near C14) Mount either R11 or R12 to select SMA or PCB antenna

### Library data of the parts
A1 = ANTENNA_HELICAL: PCB Antenna. There is nothing to buy or mount.; SymbolCreator: Altium
C11 C22 = GRM1555C1H3R6CA01D: CAP, CERM, 3.6 pF, 50 V, +/- 5%, C0G/NP0, 0402; Manufacturer: MuRata; Polarized: N; CompType: Capacitor; Value: 3.6pF; U/M: EA; Cap_F: 0.0000000000036; Tolerance_%: 5; Value1: Unknown; VDC_V: 50; Value2: 50V; TaMin_C: -55; TaMax_C: 125; Cap_Case: 0402
C12 = GRM1555C1H2R7CA01D: CAP, CERM, 2.7 pF, 50 V, +/- 5%, C0G/NP0, 0402; Manufacturer: MuRata; Polarized: N; CompType: Capacitor; Value: 2.7pF; U/M: EA; Cap_F: 0.0000000000027; Tolerance_%: 5; Value1: Unknown; VDC_V: 50; Value2: 50V; TaMin_C: -55; TaMax_C: 125; Cap_Case: 0402
C13 = GRM1555C1H6R2CA01D: CAP, CERM, 6.2 pF, 50 V, +/- 5%, C0G/NP0, 0402; Manufacturer: MuRata; Polarized: N; CompType: Capacitor; Value: 6.2pF; U/M: EA; Cap_F: 0.0000000000062; Tolerance_%: 5; Value1: Unknown; VDC_V: 50; Value2: 50V; TaMin_C: -55; TaMax_C: 125; Cap_Case: 0402
C14 = GRM1555C1H3R3CA01D: CAP, CERM, 3.3 pF, 50 V, +/- 5%, C0G/NP0, 0402; Manufacturer: MuRata; Polarized: N; CompType: Capacitor; Value: 3.3pF; U/M: EA; Cap_F: 0.0000000000033; Tolerance_%: 5; Value1: Unknown; VDC_V: 50; Value2: 50V; TaMin_C: -55; TaMax_C: 125; Cap_Case: 0402
C15 C21 = GRM1555C1H101JA01D: CAP, CERM, 100 pF, 50 V, +/- 5%, C0G/NP0, 0402; Manufacturer: MuRata; Polarized: N; CompType: Capacitor; Value: 100pF; U/M: EA; Cap_F: 0.0000000001; Tolerance_%: 5; Value1: Unknown; VDC_V: 50; Value2: 50V; TaMin_C: -55; TaMax_C: 125; Cap_Case: 0402
C16 = GRM1555C1H1R0CA01D: CAP, CERM, 1 pF, 50 V, +/- 5%, C0G/NP0, 0402; Manufacturer: MuRata; Polarized: N; CompType: Capacitor; Value: 1pF; U/M: EA; Cap_F: 0.000000000001; Tolerance_%: 5; Value1: Unknown; VDC_V: 50; Value2: 50V; TaMin_C: -55; TaMax_C: 125; Cap_Case: 0402
C61 C62 C461 C471 = GRM1555C1H120JA01D: as C46 on sheet TIDA-00838_MCU
C131 C221 C342 C343 C351 C441 C451 C481 C482 = GRM155R61E104KA87D: as C5 on sheet TIDA-00838_MCU
C231 = GRM155R61A105KE15D: as C47 on sheet TIDA-00838_MCU
C331 C341 = GRM188R60J226MEA0J: CAP, CERM, 22 µF, 6.3 V, +/- 20%, X5R, 0603; Manufacturer: MuRata; Polarized: N; CompType: Capacitor; Value: 22uF; U/M: EA; Cap_F: 0.000022; Tolerance_%: 20; Value1: Unknown; VDC_V: 6.3; Value2: 6.3V; TaMin_C: -55; TaMax_C: 85; Cap_Case: 0603
J4 = BB02-BS101-KA8-025B00: as J13 on sheet TIDA-00838_MCU
J5 = BB02-BS101-KA8-025B00: Header, 1.27mm, 5x2, SMT; Manufacturer: GradConn; SymbolCreator: a0412235; U/M: EA; Value: DNP
J6 = SASF546-P26-X1: Connector, SMA,Vertical, Thru hole w/SMT center pin; Manufacturer: Lighthorse Technologies; SymbolCreator: X0208326; U/M: EA
J9 J11 J17 = 850-10-004-10-001101: as J15 on sheet TIDA-00838_MCU
J21 = GRPB051VWVN-RC: Header, 50mil, 5x1, Gold, TH; Manufacturer: Sullins Connector Solutions; SymbolCreator: a0412235; U/M: EA
L11 = LQW15AN18NJ00D: Inductor, Wirewound, 18 nH, 0.37 A, 0.27 ohm, SMD; Manufacturer: MuRata; Value: 18nH; Ind_H: 18.0E-9; Imax_A: 0.37; DCR_ohm: 0.27; Value2: 0.37A
L12 L21 = LQW15AN7N5G00D: Inductor, Wirewound, 7.5 nH, 0.57 A, 0.13 ohm, SMD; Manufacturer: MuRata; Value: 7.5nH; Ind_H: 7.5E-9; Imax_A: 0.57; Irms: 0.57A @ C rise; DCR_ohm: 0.13; Value2: 0.57A
L13 L14 = LQW15AN6N8G00D: Inductor, Wirewound, 6.8 nH, 0.7 A, 0.09 ohm, SMD; Manufacturer: MuRata; Value: 6.8nH; Ind_H: 6.8E-9; Imax_A: 0.7; DCR_ohm: 0.09; Value2: 0.7A
L15 = LQW15AN12NJ00D: Inductor, Wirewound, 12 nH, 0.5 A, 0.14 ohm, SMD; Manufacturer: MuRata; Value: 12nH; Ind_H: 12.0E-9; Imax_A: 0.5; DCR_ohm: 0.14; Value2: 0.5A
L331 = MLZ2012N6R8LT000: Inductor, Multilayer, Ferrite, 6.8 µH, 0.11 A, 0.25 ohm, SMD; Manufacturer: TDK; Value: 6.8uH; Ind_H: 6.8E-6; ValueDisplayed: 6.8µH; Imax_A: 0.11; Irms: 0.55A @ 20C rise; Isat: 0.11A @ 50% inductance drop; DCR_ohm: 0.25; Value2: 0.11A
R11 R12 = CRCW04020000Z0ED: as R22 on sheet TIDA-00838_MCU
R351 = ERJ-2RKF1003X: RES, 100 k, 1%, 0.1 W, 0402; Manufacturer: Panasonic; CompType: Resistor; Value: 100k; Res_ohm: 100000; Tolerance_%: 1; Power_W: 0.1; Value2: 0.1W; VDC_V: 50; TempCo: 100 ppm/C; EIA_Code: E96; U/M: EA
U5 = CC1310F128RGZR: Sub-1 GHz and 2.4 GHz Multi-standard RF IC Family, RGZ0048A; Alternate PartNumber: CC1310F128RGZT; Manufacturer: Texas Instruments; SymbolCreator: Altium; U/M: EA
Y1 = FC-135 32.7680KA-A3: Crystal, 32.768 KHz, 12.5 pF, SMD; Manufacturer: Epson; SymbolCreator: a0412235; U/M: EA; TaMin_C: -40; TaMax_C: 85; Frequency Stability: ±20ppm
Y2 = TSX-3225 24.0000MF20G-AC3: Crystal, 24 MHz, 9 pF, SMD; Manufacturer: Epson; SymbolCreator: a0412235; U/M: EA; TaMin_C: -40; TaMax_C: 85; Frequency Stability: ±20ppm

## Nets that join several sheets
GND: TIDA-00838_MCU (20 pins), TIDA-00838_RF (35 pins)
VCC_430: TIDA-00838_MCU (5 pins), TIDA-00838_RF (12 pins)
DIO_1: TIDA-00838_MCU (J14.3), TIDA-00838_RF (U5.6)
DIO_4: TIDA-00838_MCU (J14.2), TIDA-00838_RF (U5.9)
DIO_5: TIDA-00838_MCU (J14.1), TIDA-00838_RF (U5.10)
UART_RX: TIDA-00838_MCU (J16.1 U4.24), TIDA-00838_RF (U5.7)
UART_TX: TIDA-00838_MCU (J16.2 U4.23), TIDA-00838_RF (U5.8)

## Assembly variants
001: not fitted FID1 FID2 FID3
